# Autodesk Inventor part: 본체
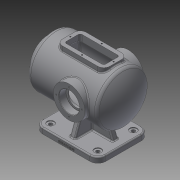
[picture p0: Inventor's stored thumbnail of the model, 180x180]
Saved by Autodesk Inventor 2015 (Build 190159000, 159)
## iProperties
Created: 2021-11
Part Number: 본체
Material: 일반
Document SubType Name: Modeling
Designer: 101256544
Density: 1 g/cm^3
Appearance: 기본값
Author: 101256544
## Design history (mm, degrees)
sketch "스케치1"
  geometry: L1 (80, -65)-(-80, -65); L2 (-80, -65)-(-80, 65); L3 (-80, 65)-(80, 65); L4 (80, 65)-(80, -65); L5 (80, -65)-(-80, 65); L6 (-80, -65)-(80, 65); 1 further point
  constraints: 12 end point, 2 midpoint, 2 parallel, 1 horizontal, 1 perpendicular
  dimensions: "d0" = 160 distance of L2.end L3.end; "d1" = 130 distance of L1.end L2.end
extrude "돌출1" new body sketch "스케치1" distance "d2" = 14; taper "d3" = 0 deg
fillet "모깎기1" dims "d4" = 20
sketch "스케치2"
  geometry: A1 r 20 centre (60, 45) between (80, 45) and (60, 65) reference; A2 r 20 centre (-60, 45) between (-60, 65) and (-80, 45) reference; A3 r 20 centre (-60, -45) between (-80, -45) and (-60, -65) reference; A4 r 20 centre (60, -45) between (60, -65) and (80, -45) reference; 1 further point
hole "구멍1" sketch "스케치2" at (-60, -45), (-60, 45), (60, -45), (60, 45) diameter "d5" = 9; stored, may be unused: countersink angle "d9" = 90 deg, drill point angle "d11" = 118 deg; dims "d6" = 6, "d7" = 18, "d8" = 2, "d10" = 8
sketch "스케치3"
  geometry: L1 (7, -50)-(-7, -50); L2 (-7, -50)-(-7, 50); L3 (-7, 50)-(7, 50); L4 (7, 50)-(7, -50); L5 (7, -50)-(-7, 50); L6 (-7, -50)-(7, 50); 1 further point
  constraints: 12 end point, 2 midpoint, 2 parallel, 1 horizontal, 1 perpendicular
  dimensions: "d12" = 14 distance of L2.end L3.end; "d13" = 100 distance of L3.end L1.start
extrude "돌출2" join sketch "스케치3" distance "d14" = 100; taper "d15" = 0 deg
feature "면 기울기1" dims angle "d16" = 20 deg
sketch "스케치4"
  geometry: L1 (60, -7)-(-60, -7); L2 (-60, -7)-(-60, 7); L3 (-60, 7)-(60, 7); L4 (60, 7)-(60, -7); L5 (60, -7)-(-60, 7); L6 (-60, -7)-(60, 7); 1 further point
  constraints: 12 end point, 2 midpoint, 2 parallel, 1 horizontal, 1 perpendicular
  dimensions: "d17" = 14 distance of L1.end L2.end; "d18" = 120 distance of L1.start L1.end
extrude "돌출3" join sketch "스케치4" distance "d19" = 100; taper "d20" = 0 deg
feature "면 기울기2" dims angle "d21" = 20 deg
sketch "스케치5"
  geometry: L1 (80, 0)-(-80, 0) reference; L2 (-80, 0)-(-80, 14) reference; L3 (-80, 14)-(-60, 14) reference; L4 (-60, 14)-(-23.603, 114) reference; L5 (-23.603, 114)-(23.603, 114) reference; L6 (23.603, 114)-(60, 14) reference; L7 (60, 14)-(80, 14) reference; L8 (80, 14)-(80, 0) reference; L9 (100, 179)-(-75.993, 179); L10 (-100, 114)-(110, 114); L11 (110, 114)-(110, 161.5); L12 (110, 161.5)-(100, 161.5); L13 (100, 161.5)-(100, 179); A1 r 100 centre (0, 114) between (-75.993, 179) and (-100, 114); 1 further point
  constraints: 10 end point, 2 horizontal, 2 point on circle, 1 centre point, 1 collinear, 1 parallel, 1 perpendicular, 1 point on line
  dimensions: "d22" = 30 distance between parallel lines of L8 L11; "d24" = 10 distance between parallel lines of L11 L13; "d25" = 47.5 distance between parallel lines of L10 L12; "d27" = 100 radius of A1; "d28" = 210 distance from line of L10.start L11; "d29" = 65 distance between parallel lines of L10 L9
revolve "회전1" sketch "스케치5" stored, may be unused: angle "d30" = 90 deg
sketch "스케치7"
  geometry: C1 r 47.5 at (0, 0) reference; C2 r 32.5 at (0, 0); 1 further point
  constraints: 1 centre point, 1 coincident
  dimensions: "d33" = 65 diameter of C2
extrude "돌출4" cut sketch "스케치7" distance "d34" = 25; taper "d35" = 0 deg
sketch "스케치6"
  geometry: L1 (80, 0)-(-80, 0) reference; L2 (-80, 0)-(-80, 14) reference; L3 (-80, 14)-(-60, 14) reference; L4 (-60, 14)-(-47.261, 49) reference; L5 (-47.261, 49)-(-75.993, 49) reference; L6 (-75.993, 179)-(100, 179) reference; L7 (100, 179)-(100, 161.5) reference; L8 (100, 161.5)-(110, 161.5) reference; L9 (110, 161.5)-(110, 146.5) reference; L10 (110, 66.5)-(100, 66.5) reference; L11 (100, 66.5)-(100, 49) reference; L12 (100, 49)-(47.261, 49) reference; L13 (47.261, 49)-(60, 14) reference; L14 (60, 14)-(80, 14) reference; L15 (80, 14)-(80, 0) reference; L16 (-71.239, 169)-(85, 169); L17 (80, 0)-(-80, 0) reference; L18 (-80, 0)-(-80, 14) reference; L19 (-80, 14)-(-60, 14) reference; L20 (-60, 14)-(-47.261, 49) reference; L21 (-47.261, 49)-(-75.993, 49) reference; L22 (-75.993, 179)-(100, 179) reference; L23 (100, 179)-(100, 161.5) reference; L24 (100, 161.5)-(110, 161.5) reference; L25 (110, 161.5)-(110, 146.5) reference; L26 (110, 66.5)-(100, 66.5) reference; L27 (100, 66.5)-(100, 49) reference; L28 (100, 49)-(47.261, 49) reference; L29 (47.261, 49)-(60, 14) reference; L30 (60, 14)-(80, 14) reference; L31 (80, 14)-(80, 0) reference; L32 (-75.993, 49)-(100, 49) reference; L33 (-75.993, 49)-(-75.993, 179) reference; L34 (110, 146.5)-(85, 146.5) reference; L35 (85, 146.5)-(85, 81.5) reference; L36 (85, 81.5)-(110, 81.5) reference; L37 (110, 81.5)-(110, 66.5) reference; L38 (110, 146.5)-(85, 146.5) reference; L39 (85, 146.5)-(85, 81.5) reference; L40 (85, 81.5)-(110, 81.5) reference; L41 (110, 81.5)-(110, 66.5) reference; L42 (85, 114)-(85, 169); L43 (85, 114)-(-90, 114); A1 r 100 centre (0, 114) between (-75.993, 179) and (-75.993, 49) reference; A2 r 90 centre (0, 114) between (-71.239, 169) and (-90, 114); A3 r 100 centre (0, 114) between (-75.993, 179) and (-75.993, 49) reference; 1 further point
  constraints: 6 end point, 2 point on circle, 1 centre point, 1 collinear, 1 horizontal, 1 perpendicular, 1 point on line, 1 vertical
  dimensions: "d31" = 10 radial gap between concentric circles of A1 A2; "d36" = 10 distance between parallel lines of L6 L16
revolve "회전2" sketch "스케치6" stored, may be unused: angle "d37" = 90 deg
node "작업 평면1"
sketch "스케치8"
  geometry: L1 (60, 30)-(-60, 30); L2 (-60, 30)-(-60, -30); L3 (-60, -30)-(60, -30); L4 (60, -30)-(60, 30); L5 (100, -65)-(100, 65) reference; L6 (110, -47.5)-(110, 47.5) reference; 3 further points
  constraints: 8 end point, 2 midpoint, 2 parallel, 1 horizontal, 1 horizontal alignment, 1 perpendicular
  dimensions: "d39" = 120 distance of L1.start L1.end; "d40" = 60 distance of L1.end L2.end; "d41" = 50 distance between parallel lines of L4 L6
extrude "돌출5" join sketch "스케치8" stored distance "d42" = 25; taper "d43" = 0 deg
sketch "스케치9"
  geometry: L1 (-60, 30)-(60, 30) reference; L2 (-60, -30)-(-60, 30) reference; L3 (60, -30)-(-60, -30) reference; L4 (60, 30)-(60, -30) reference; L5 (50, -20)-(-50, -20); L6 (-50, -20)-(-50, 20); L7 (-50, 20)-(50, 20); L8 (50, 20)-(50, -20); 1 further point
  constraints: 8 end point, 3 other
  dimensions: "d44" = 10 distance between parallel lines of L4 L8
extrude "돌출6" cut sketch "스케치9" stored distance "d45" = 25; taper "d46" = 0 deg
fillet "모깎기2" dims "d47" = 15
fillet "모깎기3" dims "d48" = 5
sketch "스케치10"
  geometry: 5 further points
  constraints: 2 horizontal alignment, 2 vertical alignment
  dimensions: "d49" = 55 distance of point (0, 0) point (-55, 0); "d50" = 25 distance of point (0, 0) point (0, 25); "d58" = 55 distance of point (55, 0) point (0, 0); "d59" = 25 distance of point (0, 0) point (0, -25)
hole "구멍2" sketch "스케치10" at (-55, 0), (0, 25), (0, -25), (55, 0) diameter "d51" = 3.242; stored, may be unused: countersink angle "d55" = 90 deg, drill point angle "d57" = 118 deg; dims "d52" = 9, "d53" = 18, "d54" = 2, "d56" = 11
node "작업 평면2"
sketch "스케치11"
  geometry: L1 (110, 66.5)-(110, 161.5) reference; C1 r 40 at (-17, 114); 2 further points
  constraints: 1 centre point, 1 horizontal alignment, 1 midpoint
  dimensions: "d61" = 80 diameter of C1; "d62" = 127 distance from line of L1 C1.centre
extrude "돌출7" join sketch "스케치11" stored distance "d63" = 25; taper "d64" = 0 deg
sketch "스케치12"
  geometry: C1 r 40 at (0, 0) reference; 1 further point
hole "구멍3" sketch "스케치12" at (0, 0) diameter "d65" = 42; stored, may be unused: countersink angle "d69" = 90 deg, drill point angle "d71" = 118 deg; dims "d66" = 9, "d67" = 52, "d68" = 18, "d70" = 75
sketch "스케치13"
  geometry: C1 r 26 at (0, 0) reference; 2 further points
  constraints: 1 vertical alignment
  dimensions: "d72" = 32.5 distance of C1.centre point (0, 32.5)
hole "구멍4" sketch "스케치13" at (0, 32.5) diameter "d73" = 3.242; stored, may be unused: countersink angle "d77" = 90 deg, drill point angle "d79" = 118 deg; dims "d74" = 11, "d75" = 52, "d76" = 18, "d78" = 13
sketch "스케치14"
  geometry: C1 r 32.5 at (0, 0) reference; 2 further points
  constraints: 1 horizontal alignment
  dimensions: "d83" = 40 distance of C1.centre point (40, 0)
hole "구멍5" sketch "스케치14" at (40, 0) diameter "d84" = 3.242; stored, may be unused: countersink angle "d88" = 90 deg, drill point angle "d90" = 118 deg; dims "d85" = 11, "d86" = 52, "d87" = 18, "d89" = 13
fillet "모깎기4" dims "d94" = 3
fillet "모깎기5" dims "d95" = 3
fillet "모깎기6" dims "d96" = 3
fillet "모깎기7" dims "d97" = 0.3
chamfer "모따기1" distance "d98" = 1; stored, may be unused: second distance "d99" = 2, angle "d100" = 45 deg
fillet "모깎기8" dims "d101" = 10
fillet "모깎기9" dims "d102" = 3
fillet "모깎기10" dims "d103" = 3
fillet "모깎기11" dims "d104" = 3
sketch "스케치15"
  geometry: L1 (120, 0)-(0, 0) reference; 3 further points
  constraints: 1 midpoint, 1 vertical alignment, 1 other
  dimensions: "d105" = 5 distance from line of L1 point (60, 5)
feature "엠보싱1" sketch "스케치15" dims "d106" = 0.5, "d107" = 0
node "솔리드1"
pattern_circular "원형 패턴1" dims angle "d81" = 360 deg
pattern_circular "원형 패턴2" dims angle "d92" = 360 deg
mirror "대칭1"
node "절단 모서리 투영1"
node "절단 모서리 투영2"
node "절단 모서리 투영3"
other parameters: "d38" = -184, "d60" = -75
